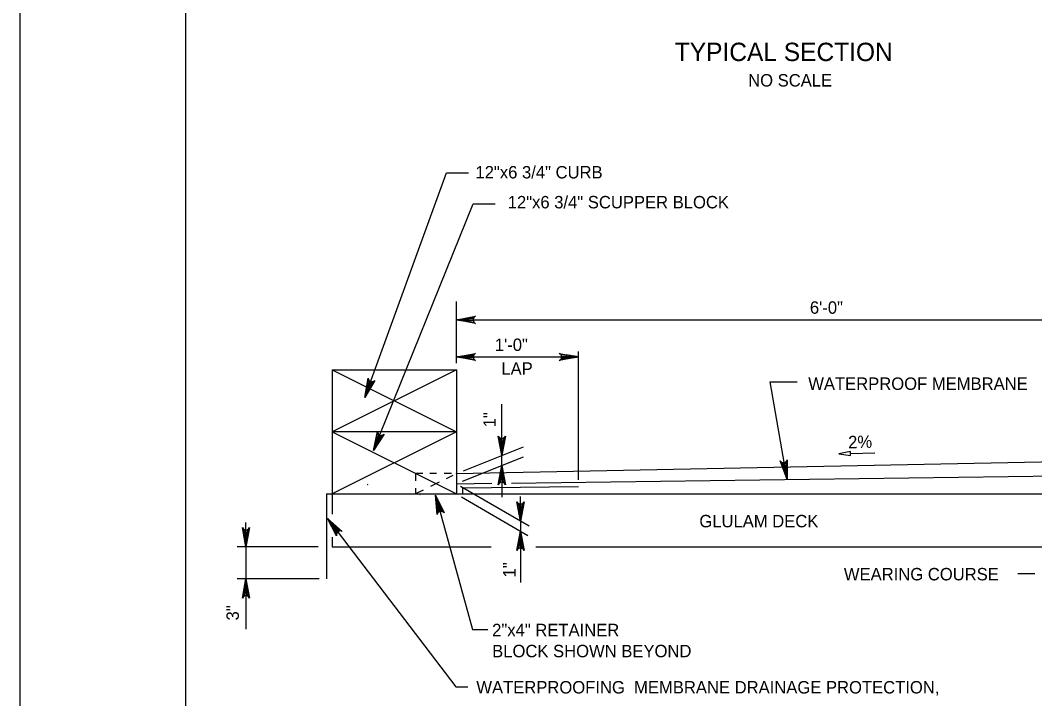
# Model space of a CAD drawing. Extents: x 638175 to 640495, y 294277 to 298435.
# Drawn here: x 638435.5 to 638680.6, y 296327.6 to 296491.5 of the extents above; entities that cross this region are included whole.
import ezdxf

# ---------------------------------------------------------------- set-up
doc = ezdxf.new("R2010")
doc.units = 0
for name, color, linetype in [('2', 7, 'Continuous'), ('3', 7, 'Continuous'), ('4', 7, 'Continuous'), ('52', 7, 'Continuous'), ('62', 7, 'Continuous'), ('PLT-BNDY', 7, 'Continuous')]:
    doc.layers.add(name, color=color, linetype=linetype)

msp = doc.modelspace()

# ---------------------------------------------------------------- linework, layer by layer
at = {"layer": '2'}
for p, q in [((638475.46, 296074.46), (638475.46, 296638.46)), ((638636.04, 296386.88), (638641.97, 296387.03)), ((638544.74, 296344.32), (638548.41, 296344.32)), ((638540.68, 296330.53), (638543.61, 296330.53))]:
    msp.add_line(p, q, dxfattribs=at)
for points in [[(638636.05, 296386.4), (638636.02, 296387.35), (638633.2, 296386.8)], [(638540.82, 296382.01), (638540.88, 296382.12), (638540.83, 296382.14)], [(638519.36, 296379.47), (638519.38, 296379.35), (638519.43, 296379.37)], [(638532, 296377.09), (638532.02, 296376.97), (638532.08, 296377)]]:
    msp.add_lwpolyline(points, close=True, dxfattribs=at)
for points in [[(638535.76, 296376.81), (638544.74, 296344.32)], [(638509.72, 296371.19), (638540.68, 296330.53)]]:
    msp.add_lwpolyline(points, dxfattribs=at)
at = {"layer": '3'}
for p, q in [((638510.8, 296407.11), (638540.82, 296407.11)), ((638510.8, 296407.11), (638540.82, 296392.1)), ((638540.82, 296407.11), (638510.8, 296392.1)), ((638510.8, 296407.11), (638510.8, 296372.22)), ((638540.82, 296407.11), (638540.82, 296377.09)), ((638540.82, 296392.1), (638510.8, 296392.1)), ((638540.82, 296392.1), (638510.8, 296377.09)), ((638510.8, 296392.1), (638540.82, 296377.09)), ((638540.82, 296382.01), (638732.17, 296385.84)), ((638554.15, 296379.73), (638774.15, 296382.67)), ((638532.71, 296382.01), (638530.98, 296382.01)), ((638530.98, 296382.01), (638530.98, 296380.23)), ((638536.01, 296382.01), (638534.43, 296382.01)), ((638539.61, 296382.01), (638537.86, 296382.01)), ((638530.98, 296378.5), (638530.98, 296377.14)), ((638540.82, 296379.55), (638549.36, 296379.67)), ((638542.34, 296378.56), (638570.35, 296378.93)), ((638542.34, 296378.56), (638542.34, 296377.09)), ((638509.44, 296377.09), (638509.46, 296356.59)), ((638509.44, 296377.09), (638542.34, 296377.09)), ((638542.34, 296377.09), (638774.5, 296377.09)), ((638510.8, 296366.63), (638510.8, 296364.3)), ((638510.8, 296364.3), (638549.21, 296364.3)), ((638560.04, 296364.3), (638735.33, 296364.3))]:
    msp.add_line(p, q, dxfattribs=at)
at = {"layer": '4'}
for p, q in [((638538.42, 296454.66), (638543.77, 296454.66)), ((638544.85, 296447.2), (638550.19, 296447.2)), ((638540.82, 296408.65), (638540.82, 296423.59)), ((638540.82, 296419.16), (638725.37, 296419.16)), ((638540.82, 296410.18), (638570.35, 296410.18)), ((638570.35, 296380.47), (638570.35, 296411.51)), ((638616.62, 296404.14), (638623.15, 296404.14)), ((638551.8, 296389.27), (638551.8, 296398.78)), ((638542.52, 296382.7), (638557.01, 296388.51)), ((638542.33, 296380.16), (638557.01, 296386.05)), ((638551.8, 296383.85), (638551.8, 296386.31)), ((638551.8, 296380.9), (638551.8, 296376.29)), ((638541.8, 296378.98), (638558.39, 296369.36)), ((638542.06, 296376.37), (638558.09, 296367.07)), ((638556.32, 296373.53), (638556.32, 296376.48)), ((638489.99, 296367.25), (638489.99, 296370.2)), ((638556.32, 296370.58), (638556.32, 296368.12)), ((638556.32, 296365.16), (638556.32, 296355.72)), ((638507.41, 296364.3), (638487.87, 296364.3)), ((638489.99, 296364.3), (638489.99, 296356.59)), ((638680.56, 296357.82), (638676.51, 296357.82)), ((638507.66, 296356.59), (638487.87, 296356.59)), ((638489.99, 296353.64), (638489.99, 296344.4))]:
    msp.add_line(p, q, dxfattribs=at)
for points in [[(638518.73, 296400.39), (638538.42, 296454.66)], [(638520.81, 296387.55), (638544.85, 296447.2)], [(638540.82, 296419.16), (638545.48, 296420.04), (638545.12, 296419.79), (638544.93, 296419.48), (638544.88, 296419.16), (638544.93, 296418.85), (638545.12, 296418.54), (638545.48, 296418.29), (638540.82, 296419.16), (638545.12, 296418.54), (638544.93, 296418.85), (638540.82, 296419.16), (638544.88, 296419.16), (638544.93, 296419.48), (638540.82, 296419.16), (638545.12, 296419.79)], [(638540.82, 296410.18), (638545.48, 296411.05), (638545.12, 296410.8), (638544.93, 296410.49), (638544.88, 296410.18), (638544.93, 296409.87), (638545.12, 296409.55), (638545.48, 296409.31), (638540.82, 296410.18), (638545.12, 296409.55), (638544.93, 296409.87), (638540.82, 296410.18), (638544.88, 296410.18), (638544.93, 296410.49), (638540.82, 296410.18), (638545.12, 296410.8)], [(638570.35, 296410.18), (638565.68, 296409.31), (638566.04, 296409.55), (638566.23, 296409.87), (638566.28, 296410.18), (638566.23, 296410.49), (638566.04, 296410.8), (638565.68, 296411.05), (638570.35, 296410.18), (638566.04, 296410.8), (638566.23, 296410.49), (638570.35, 296410.18), (638566.28, 296410.18), (638566.23, 296409.87), (638570.35, 296410.18), (638566.04, 296409.55)], [(638518.73, 296400.39), (638519.5, 296405.07), (638519.61, 296404.65), (638519.85, 296404.37), (638520.12, 296404.21), (638520.43, 296404.15), (638520.79, 296404.22), (638521.15, 296404.47), (638518.73, 296400.39), (638520.79, 296404.22), (638520.43, 296404.15), (638518.73, 296400.39), (638520.12, 296404.21), (638519.85, 296404.37), (638518.73, 296400.39), (638519.61, 296404.65)], [(638620.71, 296380.62), (638616.62, 296404.14)], [(638520.81, 296387.55), (638521.74, 296392.2), (638521.84, 296391.77), (638522.06, 296391.48), (638522.33, 296391.32), (638522.64, 296391.25), (638523, 296391.31), (638523.36, 296391.55), (638520.81, 296387.55), (638523, 296391.31), (638522.64, 296391.25), (638520.81, 296387.55), (638522.33, 296391.32), (638522.06, 296391.48), (638520.81, 296387.55), (638521.84, 296391.77)], [(638551.82, 296386.43), (638550.94, 296391.09), (638551.19, 296390.73), (638551.5, 296390.54), (638551.82, 296390.49), (638552.13, 296390.54), (638552.44, 296390.73), (638552.69, 296391.09), (638551.82, 296386.43), (638552.44, 296390.73), (638552.13, 296390.54), (638551.82, 296386.43), (638551.82, 296390.49), (638551.5, 296390.54), (638551.82, 296386.43), (638551.19, 296390.73)], [(638620.71, 296380.62), (638619.05, 296385.06), (638619.36, 296384.75), (638619.7, 296384.62), (638620.01, 296384.62), (638620.31, 296384.73), (638620.59, 296384.96), (638620.77, 296385.36), (638620.71, 296380.62), (638620.59, 296384.96), (638620.31, 296384.73), (638620.71, 296380.62), (638620.01, 296384.62), (638619.7, 296384.62), (638620.71, 296380.62), (638619.36, 296384.75)], [(638551.82, 296383.97), (638552.69, 296379.31), (638552.44, 296379.66), (638552.13, 296379.85), (638551.82, 296379.9), (638551.5, 296379.85), (638551.19, 296379.66), (638550.94, 296379.31), (638551.82, 296383.97), (638551.19, 296379.66), (638551.5, 296379.85), (638551.82, 296383.97), (638551.82, 296379.9), (638552.13, 296379.85), (638551.82, 296383.97), (638552.44, 296379.66)], [(638556.32, 296370.56), (638555.44, 296375.22), (638555.69, 296374.86), (638556, 296374.68), (638556.32, 296374.62), (638556.63, 296374.68), (638556.94, 296374.86), (638557.19, 296375.22), (638556.32, 296370.56), (638556.94, 296374.86), (638556.63, 296374.68), (638556.32, 296370.56), (638556.32, 296374.62), (638556, 296374.68), (638556.32, 296370.56), (638555.69, 296374.86)], [(638489.99, 296364.3), (638489.11, 296368.96), (638489.36, 296368.6), (638489.67, 296368.41), (638489.99, 296368.36), (638490.3, 296368.41), (638490.61, 296368.6), (638490.86, 296368.96), (638489.99, 296364.3), (638490.61, 296368.6), (638490.3, 296368.41), (638489.99, 296364.3), (638489.99, 296368.36), (638489.67, 296368.41), (638489.99, 296364.3), (638489.36, 296368.6)], [(638556.32, 296368.1), (638557.2, 296363.44), (638556.95, 296363.8), (638556.63, 296363.98), (638556.32, 296364.03), (638556.01, 296363.98), (638555.7, 296363.8), (638555.45, 296363.44), (638556.32, 296368.1), (638555.7, 296363.8), (638556.01, 296363.98), (638556.32, 296368.1), (638556.32, 296364.03), (638556.63, 296363.98), (638556.32, 296368.1), (638556.95, 296363.8)], [(638489.99, 296356.59), (638490.86, 296351.93), (638490.61, 296352.29), (638490.3, 296352.47), (638489.99, 296352.53), (638489.67, 296352.47), (638489.36, 296352.29), (638489.11, 296351.93), (638489.99, 296356.59), (638489.36, 296352.29), (638489.67, 296352.47), (638489.99, 296356.59), (638489.99, 296352.53), (638490.3, 296352.47), (638489.99, 296356.59), (638490.61, 296352.29)]]:
    msp.add_lwpolyline(points, dxfattribs=at)
for points in [[(638543.77, 296419.66), (638543.77, 296418.67), (638540.82, 296419.16)], [(638543.77, 296410.67), (638543.77, 296409.69), (638540.82, 296410.18)], [(638567.39, 296410.67), (638567.39, 296409.69), (638570.35, 296410.18)], [(638518.73, 296400.39), (638518.8, 296400.49), (638518.75, 296400.51)], [(638520.81, 296387.55), (638520.88, 296387.65), (638520.82, 296387.67)], [(638551.31, 296389.27), (638552.29, 296389.27), (638551.8, 296386.31)], [(638540.82, 296382.01), (638540.88, 296382.12), (638540.83, 296382.14)], [(638551.31, 296380.9), (638552.29, 296380.9), (638551.8, 296383.85)], [(638620.71, 296380.62), (638620.45, 296383.57), (638619.96, 296383.49)], [(638519.36, 296379.47), (638519.38, 296379.35), (638519.43, 296379.37)], [(638532, 296377.09), (638532.02, 296376.97), (638532.08, 296377)], [(638555.82, 296373.53), (638556.81, 296373.53), (638556.32, 296370.58)], [(638555.82, 296365.16), (638556.81, 296365.16), (638556.32, 296368.12)], [(638489.49, 296367.25), (638490.48, 296367.25), (638489.99, 296364.3)], [(638489.49, 296353.64), (638490.48, 296353.64), (638489.99, 296356.59)]]:
    msp.add_lwpolyline(points, close=True, dxfattribs=at)
at = {"layer": '52'}
for points in [[(638535.76, 296376.81), (638537.84, 296372.55), (638537.68, 296372.69), (638537.51, 296372.83), (638537.33, 296372.88), (638537.16, 296372.93), (638537, 296372.91), (638536.84, 296372.9), (638536.7, 296372.83), (638536.56, 296372.76), (638536.43, 296372.63), (638536.3, 296372.5), (638536.23, 296372.29), (638536.16, 296372.09), (638535.76, 296376.81), (638536.23, 296372.29), (638536.3, 296372.5), (638535.76, 296376.81), (638536.43, 296372.63), (638536.56, 296372.76), (638535.76, 296376.81), (638536.7, 296372.83), (638536.84, 296372.9), (638535.76, 296376.81), (638537, 296372.91), (638537.16, 296372.93), (638535.76, 296376.81), (638537.33, 296372.88), (638537.51, 296372.83), (638535.76, 296376.81), (638537.68, 296372.69)], [(638509.72, 296371.19), (638513.26, 296368.03), (638512.85, 296368.16), (638512.48, 296368.12), (638512.2, 296367.97), (638511.99, 296367.74), (638511.86, 296367.4), (638511.88, 296366.96), (638509.72, 296371.19), (638511.86, 296367.4), (638511.99, 296367.74), (638509.72, 296371.19), (638512.2, 296367.97), (638512.48, 296368.12), (638509.72, 296371.19), (638512.85, 296368.16)]]:
    msp.add_lwpolyline(points, dxfattribs=at)
at = {"layer": '62'}
for p, q in [((638536.68, 296379.94), (638534.57, 296378.89)), ((638539.97, 296381.59), (638538.32, 296380.77)), ((638532.82, 296378.01), (638530.98, 296377.09))]:
    msp.add_line(p, q, dxfattribs=at)
at = {"layer": 'PLT-BNDY'}
msp.add_lwpolyline([(638435.46, 296653.46), (639276.46, 296653.46), (639276.46, 296059.46), (638435.46, 296059.46)], close=True, dxfattribs=at)

# ---------------------------------------------------------------- texts
at = {"layer": '4'}
for s, height, p in [('TYPICAL SECTION', 4.4292, (638593.6, 296481.65)), ('NO SCALE', 3, (638611.32, 296475.5)), ('12"x6 3/4" CURB', 3, (638545.44, 296453.3)), ('12"x6 3/4" SCUPPER BLOCK', 3, (638553.23, 296446.07)), ('6\'-0"', 3, (638626.24, 296420.62)), ('1\'-0"', 3, (638550.12, 296411.63)), ('LAP', 3, (638551.69, 296405.88)), ('WATERPROOF MEMBRANE', 3, (638625.84, 296402.23)), ('GLULAM DECK', 3, (638599.53, 296369.03)), ('WEARING COURSE', 3, (638634.45, 296356.22)), ('2"x4" RETAINER', 3, (638549.47, 296342.73)), ('BLOCK SHOWN BEYOND', 3, (638549.47, 296337.65)), ('WATERPROOFING  MEMBRANE DRAINAGE PROTECTION,', 3, (638545.65, 296328.9))]:
    msp.add_text(s, height=height, dxfattribs=at).set_placement(p)
for s, rotation, p in [('1"', 90, (638550.35, 296393.2)), ('2%', 1.5039, (638635.52, 296388.1)), ('1"', 90, (638555.12, 296356.92)), ('3"', 90, (638488.27, 296346.54))]:
    msp.add_text(s, height=3, rotation=rotation, dxfattribs=at).set_placement(p)

doc.saveas('drawing.dxf')
